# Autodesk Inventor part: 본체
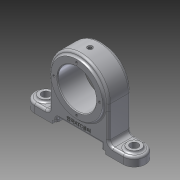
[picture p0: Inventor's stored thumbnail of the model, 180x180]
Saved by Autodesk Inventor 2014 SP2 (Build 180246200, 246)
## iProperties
Created: 2019-05
Part Number: 본체
Material: 알루미늄 6061
Document SubType Name: Modeling
Designer: gs
Density: 2.71 g/cm^3
Appearance: 알루미늄 - 평지
Author: gs
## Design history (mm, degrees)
sketch "스케치1"
  geometry: L1 (-18, 0)-(18, 0); L2 (-18, 0)-(-18, 35); L3 (-18, 35)-(-15, 35); L4 (-15, 35)-(-15, 40); L5 (-15, 40)-(15, 40); L6 (15, 40)-(15, 35); L7 (15, 35)-(18, 35); L8 (18, 35)-(18, 0); 2 further points
  constraints: 16 end point, 3 parallel, 3 perpendicular, 2 collinear, 1 coincident, 1 horizontal, 1 horizontal alignment, 1 midpoint
  dimensions: "d1" = 36 distance of L1.start L1.end; "d2" = 80 diameter of L5 L1; "d3" = 70 diameter of L3 L1; "d4" = 3 distance of L2.end L3.end
revolve "회전1" sketch "스케치1" stored, may be unused: angle "d5" = 90 deg
node "작업 평면1"
sketch "스케치2"
  geometry: L1 (-18, -35)-(-18, 35) reference; L2 (-18, 35)-(-15, 35) reference; L3 (-15, 35)-(-15, 40) reference; L4 (-15, 40)-(15, 40) reference; L5 (15, 40)-(15, 35) reference; L6 (15, 35)-(18, 35) reference; L7 (18, 35)-(18, -35) reference; L8 (18, -35)-(15, -35) reference; L9 (15, -35)-(15, -40) reference; L10 (15, -40)-(-15, -40) reference; L11 (-15, -40)-(-15, -35) reference; L12 (-15, -35)-(-18, -35) reference; L13 (-18, 0)-(18, 0); L14 (-18, 26)-(18, 26); 1 further point
  constraints: 4 end point, 2 midpoint, 2 point on line, 1 perpendicular
  dimensions: "d7" = 52 diameter of L14 L13
revolve "회전2" sketch "스케치2" stored, may be unused: angle "d8" = 90 deg
node "작업 평면2"
sketch "스케치3"
  geometry: L1 (0, -60)-(0, 60); L2 (15, -60)-(15, 60); L3 (-15, 60)-(-15, -60); A1 r 15 centre (0, -60) between (-15, -60) and (15, -60); A2 r 15 centre (0, 60) between (15, 60) and (-15, 60); 2 further points
  constraints: 8 end point, 4 point on circle, 4 tangent, 2 centre point, 1 coincident, 1 midpoint, 1 parallel, 1 vertical
  dimensions: "d10" = 30 distance between parallel lines of L3 L2; "d11" = 120 distance of L1.end L1.start
extrude "돌출1" join sketch "스케치3" distance "d12" = 12; taper "d13" = 0 deg
node "작업 평면3"
sketch "스케치4"
  geometry: L1 (48, 75)-(60, 75) reference; L2 (60, 75)-(60, -75) reference; L3 (60, -75)-(48, -75) reference; L4 (48, -75)-(48, 75) reference; L5 (0, -40)-(48, -40); L6 (0, 40)-(48, 40); C1 r 26 at (0, 0) reference; A1 r 40 centre (0, 0) between (0, -40) and (0, 40) reference; 1 further point
  constraints: 4 end point, 2 perpendicular, 2 point on circle, 2 point on line, 2 tangent
extrude "돌출2" join sketch "스케치4" stored distance "d15" = 30; taper "d16" = 0 deg
sketch "스케치5"
  geometry: L1 (-15, -60)-(-15, 60) reference; L2 (15, 60)-(15, -60) reference; L3 (-15, -36)-(15, -36); L4 (15, -36)-(15, 36); L5 (15, 36)-(-15, 36); L6 (-15, 36)-(-15, -36); 1 further point
  constraints: 8 end point, 2 parallel, 2 point on line, 1 horizontal, 1 perpendicular
  dimensions: "d17" = 72 distance of L5.end L3.start; "d18" = 36 vertical distance of point (0, 0) L3.start
extrude "돌출3" cut sketch "스케치5" distance "d19" = 4; taper "d20" = 0 deg
sketch "스케치6"
  geometry: L1 (15, 36)-(15, -36) reference; L2 (-15, -36)-(-15, 36) reference; L3 (-15, -30)-(15, -30); L4 (15, -30)-(15, 30); L5 (15, 30)-(-15, 30); L6 (-15, 30)-(-15, -30); 1 further point
  constraints: 8 end point, 2 parallel, 2 point on line, 1 horizontal, 1 perpendicular
  dimensions: "d21" = 60 distance of L5.end L3.start; "d22" = 30 vertical distance of point (0, 0) L3.start
extrude "돌출4" cut sketch "스케치6" distance "d23" = 6; taper "d24" = 0 deg
node "작업 평면4"
sketch "스케치7"
  geometry: 2 further points
  constraints: 1 coincident
hole "구멍1" sketch "스케치7" at (0, 0) diameter "d26" = 4.917; stored, may be unused: countersink angle "d30" = 90 deg, drill point angle "d32" = 118 deg; dims "d27" = 8, "d28" = 7, "d29" = 1, "d31" = 10
sketch "스케치8"
  geometry: L1 (-15, -60)-(-15, -40) reference; L2 (-15, -40)-(-15, 40) reference; L3 (-15, 40)-(-15, 60) reference; L4 (15, 60)-(15, 40) reference; L5 (-15, 40)-(15, 40) reference; L6 (15, -40)-(15, -60) reference; L7 (15, 40)-(15, -40) reference; L8 (15, -40)-(-15, -40) reference; C1 r 9 at (0, 60); C2 r 9 at (0, -60); A1 r 15 centre (0, 60) between (15, 60) and (-15, 60) reference; A2 r 15 centre (0, -60) between (-15, -60) and (15, -60) reference; 1 further point
  constraints: 2 centre point, 2 coincident
  dimensions: "d33" = 18 diameter of C1; "d34" = 18 diameter of C2
extrude "돌출5" join sketch "스케치8" distance "d35" = 3; taper "d36" = 0 deg
sketch "스케치9"
  geometry: L1 (-15, -100)-(-15, -20) reference; L2 (-15, -20)-(15, -20) reference; L3 (15, -20)-(15, -100) reference; L4 (15, -100)-(-15, -100) reference; C1 r 9 at (0, -120) reference; C2 r 9 at (0, 0) reference; C3 r 5.5 at (0, -120); C4 r 5.5 at (0, 0); 1 further point
  constraints: 2 centre point, 2 coincident
  dimensions: "d37" = 11 diameter of C3; "d38" = 11 diameter of C4
extrude "돌출6" cut sketch "스케치9" stored distance "d39" = 3; taper "d40" = 0 deg
sketch "스케치10" dims "d41" = 62
  geometry: C1 r 26 at (0, 0) reference; C2 r 35 at (0, 0) reference; 2 further points
  constraints: 2 vertical alignment, 1 coincident, 2 other
hole "구멍2" sketch "스케치10" at (0, 31) diameter "d42" = 3.242; stored, may be unused: countersink angle "d46" = 90 deg, drill point angle "d48" = 118 deg; dims "d43" = 6, "d44" = 7, "d45" = 1, "d47" = 8
node "작업 평면5"
node "작업 평면6"
sketch "스케치12"
  geometry: L1 (-90, 10)-(-30, 10) reference; A1 r 40 centre (-60, 60) between (-20, 60) and (-100, 60) reference; 1 further point
  constraints: 1 vertical alignment, 1 other
  dimensions: "d57" = 7 distance from line of point (-60, 17) L1
feature "엠보싱1" sketch "스케치12" dims "d1" = 36, "d2" = 80, "d3" = 70, "d4" = 3, "d58" = 0.5, "d59" = 0
sketch "스케치13"
  geometry: C1 r 1.5 at (0, 26); 1 further point
  constraints: 2 vertical alignment, 1 centre point, 1 other
  dimensions: "d60" = 3 diameter of C1
extrude "돌출8" cut sketch "스케치13" stored distance "d61" = 0; taper "d62" = 0 deg
chamfer "모따기1" distance "d63" = 1; stored, may be unused: second distance "d64" = 2, angle "d65" = 45 deg
fillet "모깎기1" dims "d66" = 3
fillet "모깎기2" dims "d67" = 6
fillet "모깎기3" dims "d68" = 3
fillet "모깎기4" dims "d69" = 3
fillet "모깎기5" dims "d70" = 3
node "솔리드1"
pattern_circular "원형 패턴1" dims angle "d50" = 360 deg
mirror "대칭1"
node "절단 모서리 투영1"
node "절단 모서리 투영2"
node "절단 모서리 투영3"
node "절단 모서리 투영4"
other parameters: "d6" = 0, "d14" = 0, "d52" = 0, "d53" = 36
